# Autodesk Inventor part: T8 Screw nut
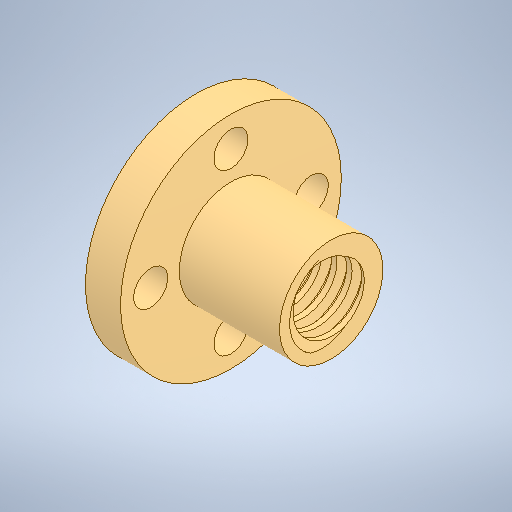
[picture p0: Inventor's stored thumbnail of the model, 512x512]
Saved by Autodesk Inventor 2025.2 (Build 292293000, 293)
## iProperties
Created: 2021-12
Part Number: T8 Screw nut
Material: Steel
Document SubType Name: Modeling
Designer: BennF
Density: 7.85 g/cm^3
Appearance: Default
Title: C:/Users/danig/Dropbox/Fusion/Perfil/T8 Screw nut v0.step
Sending System: Autodesk Translation Framework v10.10.0.1391
Preprocessor: ST-DEVELOPER v18.1
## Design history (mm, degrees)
feature "Body1"
body "Solid1"
